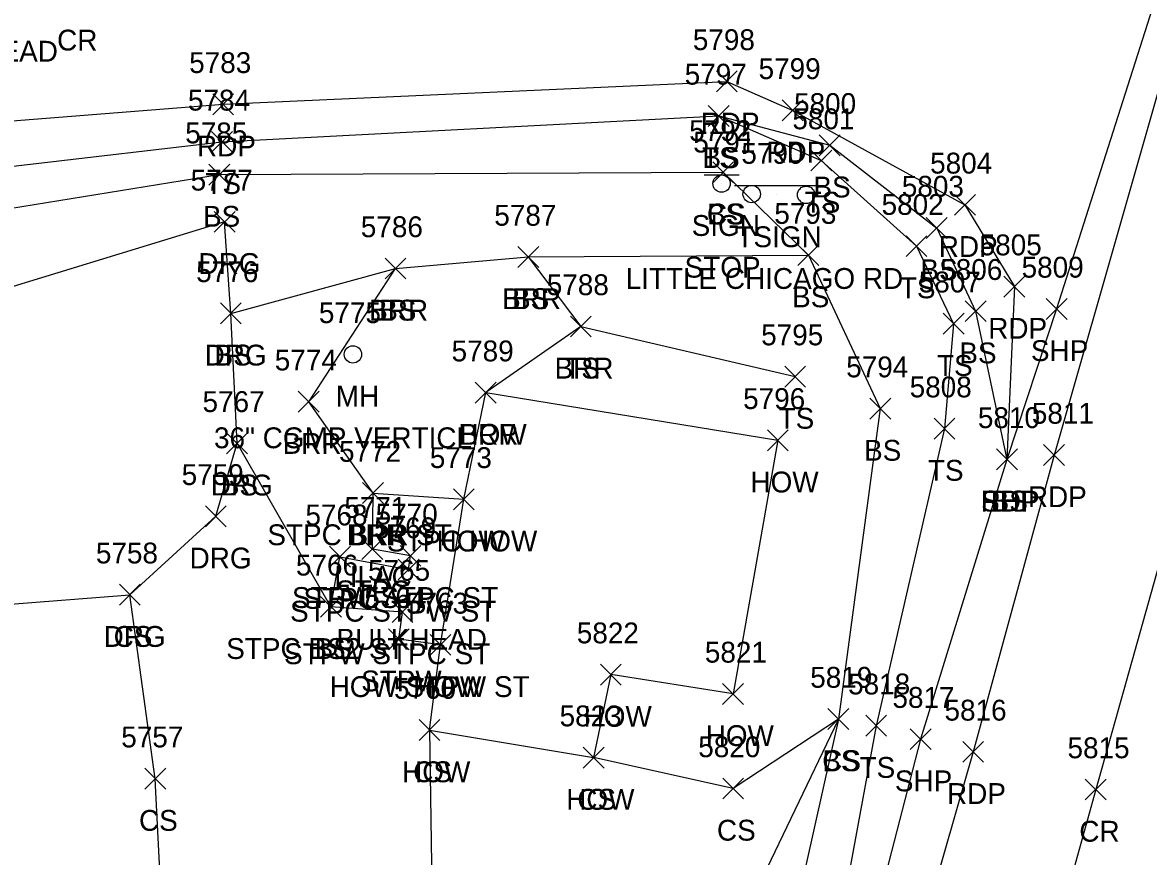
# Model space of a CAD drawing. Extents: x 1443912 to 1445411, y 621446 to 623693.
# Drawn here: x 1444608.9 to 1444716.8, y 622472.5 to 622552.5 of the extents above; entities that cross this region are included whole.
import ezdxf

# ---------------------------------------------------------------- set-up
doc = ezdxf.new("R2010")
doc.units = 0
for name, color, linetype in [('L_A', 7, 'Continuous'), ('L_C', 7, 'Continuous'), ('L_I', 7, 'Continuous'), ('L_TIC', 7, 'Continuous'), ('LABL', 7, 'Continuous'), ('LBC', 7, 'Continuous'), ('LBF', 7, 'Continuous'), ('LELB', 7, 'Continuous'), ('P_A', 7, 'Continuous'), ('P_I', 7, 'Continuous'), ('P_TIC', 7, 'Continuous'), ('PET', 7, 'Continuous'), ('PRC', 7, 'Continuous'), ('PSP', 7, 'Continuous'), ('R_A', 7, 'Continuous'), ('R_I', 7, 'Continuous'), ('R_TIC', 7, 'Continuous'), ('RDG', 7, 'Continuous'), ('S_A', 7, 'Continuous'), ('S_C', 7, 'Continuous'), ('S_I', 7, 'Continuous'), ('SSGN', 7, 'Continuous'), ('U_A', 7, 'Continuous'), ('U_C', 7, 'Continuous'), ('U_I', 7, 'Continuous'), ('UUMH', 7, 'Continuous')]:
    doc.layers.add(name, color=color, linetype=linetype)

msp = doc.modelspace()

# ---------------------------------------------------------------- linework, layer by layer
at = {"layer": 'L_TIC'}
for points in [[(1444674.64, 622542.57), (1444676.64, 622544.57)], [(1444676.64, 622542.57), (1444674.64, 622544.57)], [(1444674.64, 622542.57), (1444676.64, 622544.57)], [(1444676.64, 622542.57), (1444674.64, 622544.57)], [(1444627.03, 622540.08), (1444629.03, 622542.08)], [(1444629.03, 622540.08), (1444627.03, 622542.08)], [(1444685.28, 622539.75), (1444687.28, 622541.75)], [(1444687.28, 622539.75), (1444685.28, 622541.75)], [(1444684.47, 622538.29), (1444686.47, 622540.29)], [(1444686.47, 622538.29), (1444684.47, 622540.29)], [(1444626.77, 622536.94), (1444628.77, 622538.94)], [(1444628.77, 622536.94), (1444626.77, 622538.94)], [(1444675.07, 622537.16), (1444677.07, 622539.16)], [(1444677.07, 622537.16), (1444675.07, 622539.16)], [(1444675.07, 622537.16), (1444677.07, 622539.16)], [(1444677.07, 622537.16), (1444675.07, 622539.16)], [(1444695.53, 622531.82), (1444697.53, 622533.82)], [(1444697.53, 622531.82), (1444695.53, 622533.82)], [(1444693.59, 622530.08), (1444695.59, 622532.08)], [(1444695.59, 622530.08), (1444693.59, 622532.08)], [(1444656.39, 622529.04), (1444658.39, 622531.04)], [(1444658.39, 622529.04), (1444656.39, 622531.04)], [(1444656.39, 622529.04), (1444658.39, 622531.04)], [(1444658.39, 622529.04), (1444656.39, 622531.04)], [(1444683.23, 622529.22), (1444685.23, 622531.22)], [(1444685.23, 622529.22), (1444683.23, 622531.22)], [(1444683.23, 622529.22), (1444685.23, 622531.22)], [(1444685.23, 622529.22), (1444683.23, 622531.22)], [(1444643.66, 622527.94), (1444645.66, 622529.94)], [(1444645.66, 622527.94), (1444643.66, 622529.94)], [(1444643.66, 622527.94), (1444645.66, 622529.94)], [(1444645.66, 622527.94), (1444643.66, 622529.94)], [(1444627.88, 622523.63), (1444629.88, 622525.63)], [(1444629.88, 622523.63), (1444627.88, 622525.63)], [(1444699.26, 622523.84), (1444701.26, 622525.84)], [(1444701.26, 622523.84), (1444699.26, 622525.84)], [(1444661.42, 622522.38), (1444663.42, 622524.38)], [(1444663.42, 622522.38), (1444661.42, 622524.38)], [(1444661.42, 622522.38), (1444663.42, 622524.38)], [(1444663.42, 622522.38), (1444661.42, 622524.38)], [(1444697.15, 622522.64), (1444699.15, 622524.64)], [(1444699.15, 622522.64), (1444697.15, 622524.64)], [(1444681.97, 622517.57), (1444683.97, 622519.57)], [(1444683.97, 622517.57), (1444681.97, 622519.57)], [(1444652.31, 622516.03), (1444654.31, 622518.03)], [(1444654.31, 622516.03), (1444652.31, 622518.03)], [(1444652.31, 622516.03), (1444654.31, 622518.03)], [(1444654.31, 622516.03), (1444652.31, 622518.03)], [(1444635.35, 622515.16), (1444637.35, 622517.16)], [(1444637.35, 622515.16), (1444635.35, 622517.16)], [(1444690.12, 622514.5), (1444692.12, 622516.5)], [(1444692.12, 622514.5), (1444690.12, 622516.5)], [(1444696.28, 622512.58), (1444698.28, 622514.58)], [(1444698.28, 622512.58), (1444696.28, 622514.58)], [(1444628.48, 622511.17), (1444630.48, 622513.17)], [(1444630.48, 622511.17), (1444628.48, 622513.17)], [(1444680.3, 622511.46), (1444682.3, 622513.46)], [(1444682.3, 622511.46), (1444680.3, 622513.46)], [(1444702.26, 622509.63), (1444704.26, 622511.63)], [(1444704.26, 622509.63), (1444702.26, 622511.63)], [(1444641.51, 622506.4), (1444643.51, 622508.4)], [(1444643.51, 622506.4), (1444641.51, 622508.4)], [(1444641.51, 622506.4), (1444643.51, 622508.4)], [(1444643.51, 622506.4), (1444641.51, 622508.4)], [(1444650.21, 622505.8), (1444652.21, 622507.8)], [(1444652.21, 622505.8), (1444650.21, 622507.8)], [(1444650.21, 622505.8), (1444652.21, 622507.8)], [(1444652.21, 622505.8), (1444650.21, 622507.8)], [(1444638.34, 622500.3), (1444640.34, 622502.3)], [(1444640.34, 622500.3), (1444638.34, 622502.3)], [(1444641.45, 622501.02), (1444643.45, 622503.02)], [(1444643.45, 622501.02), (1444641.45, 622503.02)], [(1444645.1, 622500.38), (1444647.1, 622502.38)], [(1444647.1, 622500.38), (1444645.1, 622502.38)], [(1444645.1, 622500.38), (1444647.1, 622502.38)], [(1444647.1, 622500.38), (1444645.1, 622502.38)], [(1444644.92, 622499.07), (1444646.92, 622501.07)], [(1444646.92, 622499.07), (1444644.92, 622501.07)], [(1444644.92, 622499.07), (1444646.92, 622501.07)], [(1444646.92, 622499.07), (1444644.92, 622501.07)], [(1444618.2, 622496.65), (1444620.2, 622498.65)], [(1444620.2, 622496.65), (1444618.2, 622498.65)], [(1444637.48, 622495.49), (1444639.48, 622497.49)], [(1444639.48, 622495.49), (1444637.48, 622497.49)], [(1444637.48, 622495.49), (1444639.48, 622497.49)], [(1444639.48, 622495.49), (1444637.48, 622497.49)], [(1444644.34, 622494.99), (1444646.34, 622496.99)], [(1444646.34, 622494.99), (1444644.34, 622496.99)], [(1444644.34, 622494.99), (1444646.34, 622496.99)], [(1444646.34, 622494.99), (1444644.34, 622496.99)], [(1444643.98, 622492.38), (1444645.98, 622494.38)], [(1444645.98, 622492.38), (1444643.98, 622494.38)], [(1444647.97, 622491.84), (1444649.97, 622493.84)], [(1444649.97, 622491.84), (1444647.97, 622493.84)], [(1444647.97, 622491.84), (1444649.97, 622493.84)], [(1444649.97, 622491.84), (1444647.97, 622493.84)], [(1444664.3, 622488.99), (1444666.3, 622490.99)], [(1444666.3, 622488.99), (1444664.3, 622490.99)], [(1444676.01, 622487.14), (1444678.01, 622489.14)], [(1444678.01, 622487.14), (1444676.01, 622489.14)], [(1444686.11, 622484.73), (1444688.11, 622486.73)], [(1444688.11, 622484.73), (1444686.11, 622486.73)], [(1444686.11, 622484.73), (1444688.11, 622486.73)], [(1444688.11, 622484.73), (1444686.11, 622486.73)], [(1444686.11, 622484.73), (1444688.11, 622486.73)], [(1444688.11, 622484.73), (1444686.11, 622486.73)], [(1444689.73, 622484.09), (1444691.73, 622486.09)], [(1444691.73, 622484.09), (1444689.73, 622486.09)], [(1444646.92, 622483.67), (1444648.92, 622485.67)], [(1444648.92, 622483.67), (1444646.92, 622485.67)], [(1444646.92, 622483.67), (1444648.92, 622485.67)], [(1444648.92, 622483.67), (1444646.92, 622485.67)], [(1444646.92, 622483.67), (1444648.92, 622485.67)], [(1444648.92, 622483.67), (1444646.92, 622485.67)], [(1444662.65, 622481.03), (1444664.65, 622483.03)], [(1444664.65, 622481.03), (1444662.65, 622483.03)], [(1444662.65, 622481.03), (1444664.65, 622483.03)], [(1444664.65, 622481.03), (1444662.65, 622483.03)], [(1444662.65, 622481.03), (1444664.65, 622483.03)], [(1444664.65, 622481.03), (1444662.65, 622483.03)], [(1444620.64, 622479.01), (1444622.64, 622481.01)], [(1444622.64, 622479.01), (1444620.64, 622481.01)], [(1444676.02, 622478.07), (1444678.02, 622480.07)], [(1444678.02, 622478.07), (1444676.02, 622480.07)]]:
    msp.add_lwpolyline(points, dxfattribs=at)
at = {"layer": 'LABL'}
msp.add_lwpolyline([(1444642.51, 622507.4), (1444636.35, 622516.16), (1444644.66, 622528.94), (1444657.39, 622530.04), (1444662.42, 622523.38), (1444653.31, 622517.03)], dxfattribs=at)
at = {"layer": 'LBC'}
for points in [[(1444647.92, 622484.67), (1444648.97, 622492.84), (1444651.21, 622506.8), (1444653.31, 622517.03), (1444681.3, 622512.46), (1444677.01, 622488.14), (1444665.3, 622489.99), (1444663.65, 622482.03)], [(1444647.92, 622484.67), (1444663.65, 622482.03)]]:
    msp.add_lwpolyline(points, dxfattribs=at)
at = {"layer": 'LBF'}
for points in [[(1444646.1, 622501.38), (1444642.45, 622502.02), (1444642.51, 622507.4), (1444651.21, 622506.8)], [(1444645.34, 622495.99), (1444638.48, 622496.49), (1444639.34, 622501.3), (1444645.92, 622500.07)], [(1444645.92, 622500.07), (1444646.1, 622501.38)], [(1444648.97, 622492.84), (1444644.98, 622493.38), (1444645.34, 622495.99)]]:
    msp.add_lwpolyline(points, dxfattribs=at)
at = {"layer": 'LELB'}
for points in [[(1444421.11, 622504.89), (1444418.48, 622504.7), (1444415.25, 622506.32), (1444414.67, 622509.11), (1444420.34, 622517.15), (1444423.31, 622521.52), (1444460.25, 622525.5), (1444495.17, 622528.66), (1444538.07, 622531.66), (1444573.03, 622534.31), (1444590.73, 622536.75), (1444628.03, 622541.08), (1444675.64, 622543.57), (1444685.47, 622539.29), (1444694.59, 622531.08), (1444698.15, 622523.64), (1444697.28, 622513.58), (1444690.73, 622485.09), (1444685.42, 622456.27), (1444672.73, 622423.51)], [(1444675.64, 622543.57), (1444686.28, 622540.75), (1444696.53, 622532.82), (1444700.26, 622524.84), (1444703.26, 622510.63)], [(1444409.34, 622487.42), (1444415.25, 622506.32), (1444423.16, 622515.73), (1444423.35, 622517.79), (1444427.35, 622519.19), (1444459.99, 622522.27), (1444495.92, 622525.45), (1444537.82, 622527.87), (1444575.08, 622531.37), (1444592.28, 622532.21), (1444627.77, 622537.94), (1444676.07, 622538.16), (1444684.23, 622530.22)], [(1444657.39, 622530.04), (1444684.23, 622530.22), (1444691.12, 622515.5), (1444687.11, 622485.73), (1444673.41, 622457.14), (1444667.38, 622434.95)], [(1444628.88, 622524.63), (1444644.66, 622528.94)], [(1444662.42, 622523.38), (1444682.97, 622518.57)], [(1444638.48, 622496.49), (1444629.48, 622512.17)], [(1444626.49, 622431.4), (1444625.7, 622446.49), (1444622.58, 622461.12), (1444621.64, 622480.01), (1444619.2, 622497.65)], [(1444687.11, 622485.73), (1444681.71, 622461.51), (1444668.63, 622426.69), (1444649.03, 622429.73), (1444633.61, 622428.6)], [(1444687.11, 622485.73), (1444677.02, 622479.07), (1444663.65, 622482.03)], [(1444647.92, 622484.67), (1444648.26, 622461.14), (1444648.76, 622435.33)]]:
    msp.add_lwpolyline(points, dxfattribs=at)
at = {"layer": 'P_TIC'}
for points in [[(1444675.42, 622545.88), (1444677.42, 622547.88)], [(1444677.42, 622545.88), (1444675.42, 622547.88)], [(1444627.15, 622543.68), (1444629.15, 622545.68)], [(1444629.15, 622543.68), (1444627.15, 622545.68)], [(1444681.73, 622543.1), (1444683.73, 622545.1)], [(1444683.73, 622543.1), (1444681.73, 622545.1)], [(1444698.24, 622534.04), (1444700.24, 622536.04)], [(1444700.24, 622534.04), (1444698.24, 622536.04)], [(1444702.98, 622526.2), (1444704.98, 622528.2)], [(1444704.98, 622526.2), (1444702.98, 622528.2)], [(1444707.02, 622524.06), (1444709.02, 622526.06)], [(1444709.02, 622524.06), (1444707.02, 622526.06)], [(1444707.02, 622524.06), (1444709.02, 622526.06)], [(1444709.02, 622524.06), (1444707.02, 622526.06)], [(1444706.78, 622510.05), (1444708.78, 622512.05)], [(1444708.78, 622510.05), (1444706.78, 622512.05)], [(1444706.78, 622510.05), (1444708.78, 622512.05)], [(1444708.78, 622510.05), (1444706.78, 622512.05)], [(1444702.26, 622509.63), (1444704.26, 622511.63)], [(1444704.26, 622509.63), (1444702.26, 622511.63)], [(1444702.26, 622509.63), (1444704.26, 622511.63)], [(1444704.26, 622509.63), (1444702.26, 622511.63)], [(1444693.99, 622482.8), (1444695.99, 622484.8)], [(1444695.99, 622482.8), (1444693.99, 622484.8)], [(1444699.03, 622481.58), (1444701.03, 622483.58)], [(1444701.03, 622481.58), (1444699.03, 622483.58)], [(1444710.77, 622477.97), (1444712.77, 622479.97)], [(1444712.77, 622477.97), (1444710.77, 622479.97)]]:
    msp.add_lwpolyline(points, dxfattribs=at)
at = {"layer": 'PET'}
for points in [[(1444737.32, 622616.48), (1444732.68, 622599.46), (1444722.11, 622561.15), (1444707.78, 622511.05)], [(1443922.89, 622481.78), (1443964.16, 622485.92), (1444013.47, 622490.18), (1444063.08, 622494.61), (1444083.54, 622496.56), (1444116.52, 622499.25), (1444168.09, 622503.58), (1444210.27, 622507.18), (1444250.99, 622510.56), (1444300.66, 622515.16), (1444342.9, 622518.95), (1444378.71, 622522.5), (1444430.26, 622526.78), (1444460.19, 622529.88), (1444494.98, 622532.7), (1444537.07, 622536.56), (1444563.09, 622539.1), (1444595.4, 622542.11), (1444628.15, 622544.68), (1444676.42, 622546.88), (1444682.73, 622544.1), (1444699.24, 622535.04), (1444703.98, 622527.2), (1444703.26, 622510.63)], [(1444707.78, 622511.05), (1444700.03, 622482.58), (1444691.73, 622453.67), (1444679.73, 622411.23), (1444667.69, 622368.84), (1444653.08, 622317.67), (1444637.74, 622256.92), (1444626.42, 622209.58), (1444619.02, 622182.67), (1444605.37, 622130.08), (1444589.4, 622078.61), (1444578.44, 622026.86), (1444565.52, 621990.05), (1444556.87, 621958.17), (1444542.16, 621907.74), (1444529.8, 621863.07), (1444511.99, 621799.88), (1444498.16, 621751.76), (1444483.13, 621697.3), (1444470.84, 621653.16), (1444463.41, 621627.34), (1444449.07, 621575.52), (1444430.26, 621508.83), (1444421.17, 621471.46)]]:
    msp.add_lwpolyline(points, dxfattribs=at)
at = {"layer": 'PRC'}
msp.add_lwpolyline([(1444846.73, 622950.74), (1444829.37, 622896.11), (1444814.12, 622840.53), (1444801.7, 622795.63), (1444790.08, 622753.54), (1444778.65, 622716.11), (1444769.12, 622683.18), (1444760.94, 622654.81), (1444750.77, 622619.03), (1444741.67, 622586.01), (1444729.73, 622541.23), (1444723.42, 622520.39), (1444711.77, 622478.97), (1444703.65, 622449.63), (1444691.66, 622407.43), (1444679.51, 622365.85), (1444664.93, 622313.64), (1444649.43, 622253.98), (1444637.04, 622206.21), (1444631.31, 622178.74), (1444618.32, 622127.38), (1444604.97, 622075.74)], dxfattribs=at)
at = {"layer": 'PSP'}
for points in [[(1444735.15, 622617.37), (1444730.87, 622600.03), (1444727.75, 622590.13), (1444719.77, 622561.99), (1444708.02, 622525.06)], [(1444708.02, 622525.06), (1444703.26, 622510.63), (1444694.99, 622483.8), (1444687.65, 622455.43), (1444679.42, 622427.15), (1444669.36, 622395.79), (1444665.29, 622376.89), (1444648.73, 622318.09), (1444646.34, 622310.05), (1444631.38, 622258.8), (1444618.63, 622212.47), (1444610.54, 622185.48), (1444596.17, 622132.46), (1444585.6, 622096.58)]]:
    msp.add_lwpolyline(points, dxfattribs=at)
at = {"layer": 'R_TIC'}
for points in [[(1444627.29, 622532.41), (1444629.29, 622534.41)], [(1444629.29, 622532.41), (1444627.29, 622534.41)], [(1444627.88, 622523.63), (1444629.88, 622525.63)], [(1444629.88, 622523.63), (1444627.88, 622525.63)], [(1444628.48, 622511.17), (1444630.48, 622513.17)], [(1444630.48, 622511.17), (1444628.48, 622513.17)], [(1444626.44, 622504.17), (1444628.44, 622506.17)], [(1444628.44, 622504.17), (1444626.44, 622506.17)], [(1444618.2, 622496.65), (1444620.2, 622498.65)], [(1444620.2, 622496.65), (1444618.2, 622498.65)]]:
    msp.add_lwpolyline(points, dxfattribs=at)
at = {"layer": 'RDG'}
msp.add_lwpolyline([(1444582.15, 622486.18), (1444599.95, 622488.7), (1444599.13, 622496.08), (1444619.2, 622497.65), (1444627.44, 622505.17), (1444629.48, 622512.17), (1444628.88, 622524.63), (1444628.29, 622533.41), (1444602.15, 622525.41), (1444592.28, 622532.21), (1444590.73, 622536.75), (1444590.12, 622540.23)], dxfattribs=at)
at = {"layer": 'SSGN'}
for p, q in [((1444674.26, 622537.91), (1444677.59, 622537.91)), ((1444675.91, 622537.08), (1444675.91, 622537.08)), ((1444677.14, 622536.9), (1444685.74, 622536.9)), ((1444681.16, 622536), (1444681.16, 622536))]:
    msp.add_line(p, q, dxfattribs=at)
for centre in [(1444675.91, 622537.08), (1444678.8, 622536.07), (1444684.02, 622536)]:
    msp.add_circle(centre, 0.833, dxfattribs=at)
at = {"layer": 'UUMH'}
for p, q in [((1444640.58, 622520.7), (1444640.58, 622520.7)), ((1444641.41, 622520.7), (1444641.41, 622520.7))]:
    msp.add_line(p, q, dxfattribs=at)
msp.add_circle((1444640.58, 622520.7), 0.833, dxfattribs=at)

# ---------------------------------------------------------------- texts
at = {"layer": 'L_A'}
for s, p in [('TS', (1444674.05, 622538.57)), ('BS', (1444674.08, 622538.57)), ('TS', (1444626.44, 622536.08)), ('BS', (1444684.72, 622535.75)), ('TS', (1444683.88, 622534.29)), ('BS', (1444626.21, 622532.94)), ('CS', (1444674.51, 622533.16)), ('BS', (1444674.51, 622533.16)), ('BS', (1444694.97, 622527.82)), ('BS', (1444655.83, 622525.04)), ('BS', (1444682.67, 622525.22)), ('BS', (1444682.67, 622525.22)), ('TS', (1444693, 622526.08)), ('BS', (1444643.1, 622523.94)), ('BRR', (1444654.88, 622525.04)), ('BRR', (1444642.14, 622523.94)), ('BS', (1444627.32, 622519.63)), ('BS', (1444698.7, 622519.84)), ('TS', (1444696.56, 622518.64)), ('BRR', (1444659.91, 622518.38)), ('TS', (1444660.83, 622518.38)), ('TS', (1444681.38, 622513.57)), ('BRR', (1444633.84, 622511.16)), ('HOW', (1444650.7, 622512.03)), ('BRR', (1444650.8, 622512.03)), ('BS', (1444689.57, 622510.5)), ('TS', (1444695.69, 622508.58)), ('BS', (1444627.92, 622507.17)), ('HOW', (1444678.68, 622507.46)), ('BS', (1444701.7, 622505.63)), ('STPC BRR ST', (1444632.38, 622502.4)), ('BRR', (1444640, 622502.4)), ('STPC HOW', (1444643.84, 622501.8)), ('HOW', (1444648.6, 622501.8)), ('STPC', (1444638.96, 622497.02)), ('STPW STPC ST', (1444634.74, 622496.38)), ('STPW STPC ST', (1444634.74, 622496.38)), ('STPC', (1444635.85, 622496.3)), ('STPC STPW ST', (1444634.56, 622495.07)), ('STPC STPW ST', (1444634.56, 622495.07)), ('CS', (1444617.65, 622492.65)), ('STPC BS2 ST', (1444628.44, 622491.49)), ('STPW STPC ST', (1444633.98, 622490.99)), ('STPW STPC ST', (1444633.98, 622490.99)), ('BS', (1444636.92, 622491.49)), ('STPW', (1444641.37, 622488.38)), ('HOW STPW ST', (1444638.35, 622487.84)), ('HOW', (1444646.36, 622487.84)), ('HOW', (1444662.69, 622484.99)), ('HOW', (1444674.39, 622483.14)), ('CS', (1444685.56, 622480.73)), ('CS', (1444685.56, 622480.73)), ('BS', (1444685.56, 622480.73)), ('TS', (1444689.14, 622480.09)), ('HOW', (1444645.3, 622479.67)), ('HOW', (1444645.3, 622479.67)), ('CS', (1444646.36, 622479.67)), ('HOW', (1444661.03, 622477.03)), ('HOW', (1444661.03, 622477.03)), ('CS', (1444662.09, 622477.03)), ('CS', (1444620.08, 622475.01)), ('CS', (1444675.47, 622474.07))]:
    msp.add_text(s, height=2, dxfattribs=at).set_placement(p)
at = {"layer": 'L_C'}
for s, p in [('LILAC', (1444638.79, 622498.4)), ('BULKHEAD', (1444639.01, 622492.38)), ('BULKHEAD', (1444639.01, 622492.38))]:
    msp.add_text(s, height=2, dxfattribs=at).set_placement(p)
at = {"layer": 'L_I'}
for s, p in [('5797', (1444672.38, 622546.57)), ('5797', (1444672.38, 622546.57)), ('5784', (1444624.77, 622544.08)), ('5800', (1444682.86, 622543.75)), ('5801', (1444682.7, 622542.29)), ('5785', (1444624.51, 622540.94)), ('5792', (1444672.81, 622541.16)), ('5792', (1444672.81, 622541.16)), ('5803', (1444693.19, 622535.82)), ('5802', (1444691.25, 622534.08)), ('5787', (1444654.13, 622533.04)), ('5787', (1444654.13, 622533.04)), ('5793', (1444680.97, 622533.22)), ('5793', (1444680.97, 622533.22)), ('5786', (1444641.34, 622531.94)), ('5786', (1444641.34, 622531.94)), ('5776', (1444625.56, 622527.63)), ('5806', (1444696.87, 622527.84)), ('5788', (1444659.16, 622526.38)), ('5788', (1444659.16, 622526.38)), ('5807', (1444694.81, 622526.64)), ('5795', (1444679.71, 622521.57)), ('5789', (1444650.04, 622520.03)), ('5789', (1444650.04, 622520.03)), ('5774', (1444633.09, 622519.16)), ('5794', (1444687.86, 622518.5)), ('5808', (1444693.94, 622516.58)), ('5796', (1444677.98, 622515.46)), ('5767', (1444626.17, 622515.17)), ('5810', (1444700.48, 622513.63)), ('5772', (1444639.25, 622510.4)), ('5772', (1444639.25, 622510.4)), ('5773', (1444647.95, 622509.8)), ('5773', (1444647.95, 622509.8)), ('5771', (1444639.76, 622505.02)), ('5768', (1444636.03, 622504.3)), ('5770', (1444642.76, 622504.38)), ('5770', (1444642.76, 622504.38)), ('5769', (1444642.61, 622503.07)), ('5769', (1444642.61, 622503.07)), ('5758', (1444615.95, 622500.65)), ('5766', (1444635.12, 622499.49)), ('5766', (1444635.12, 622499.49)), ('5765', (1444642.03, 622498.99)), ('5765', (1444642.03, 622498.99)), ('5764', (1444641.67, 622496.38)), ('5763', (1444645.67, 622495.84)), ('5763', (1444645.67, 622495.84)), ('5822', (1444662.04, 622492.99)), ('5821', (1444674.31, 622491.14)), ('5819', (1444684.41, 622488.73)), ('5819', (1444684.41, 622488.73)), ('5819', (1444684.41, 622488.73)), ('5760', (1444644.52, 622487.67)), ('5760', (1444644.52, 622487.67)), ('5760', (1444644.52, 622487.67)), ('5818', (1444688.04, 622488.09)), ('5823', (1444660.39, 622485.03)), ('5823', (1444660.39, 622485.03)), ('5823', (1444660.39, 622485.03)), ('5757', (1444618.38, 622483.01)), ('5820', (1444673.68, 622482.07))]:
    msp.add_text(s, height=2, dxfattribs=at).set_placement(p)
at = {"layer": 'P_A'}
for s, p in [('CR', (1444612.23, 622549.84)), ('RDP', (1444673.91, 622541.88)), ('RDP', (1444625.64, 622539.68)), ('RDP', (1444680.21, 622539.1)), ('RDP', (1444696.73, 622530.04)), ('RDP', (1444701.47, 622522.2)), ('SHP', (1444705.56, 622520.06)), ('SHP', (1444705.56, 622520.06)), ('SHP', (1444700.79, 622505.63)), ('RDP', (1444700.75, 622505.63)), ('RDP', (1444705.27, 622506.05)), ('RDP', (1444705.27, 622506.05)), ('SHP', (1444692.52, 622478.8)), ('RDP', (1444697.52, 622477.58)), ('CR', (1444710.2, 622473.97))]:
    msp.add_text(s, height=2, dxfattribs=at).set_placement(p)
at = {"layer": 'P_I'}
for s, p in [('5798', (1444673.16, 622549.88)), ('5783', (1444624.89, 622547.68)), ('5799', (1444679.46, 622547.1)), ('5804', (1444695.9, 622538.04)), ('5805', (1444700.65, 622530.2)), ('5809', (1444704.67, 622528.06)), ('5809', (1444704.67, 622528.06)), ('5810', (1444700.48, 622513.63)), ('5810', (1444700.48, 622513.63)), ('5811', (1444705.65, 622514.05)), ('5811', (1444705.65, 622514.05)), ('5817', (1444692.29, 622486.8)), ('5816', (1444697.28, 622485.58)), ('5815', (1444709.07, 622481.97))]:
    msp.add_text(s, height=2, dxfattribs=at).set_placement(p)
at = {"layer": 'R_A'}
for p in [(1444625.78, 622528.41), (1444626.37, 622519.63), (1444626.96, 622507.17), (1444624.93, 622500.17), (1444616.69, 622492.65)]:
    msp.add_text('DRG', height=2, dxfattribs=at).set_placement(p)
at = {"layer": 'R_I'}
for s, p in [('5777', (1444625.03, 622536.41)), ('5776', (1444625.56, 622527.63)), ('5767', (1444626.17, 622515.17)), ('5759', (1444624.17, 622508.17)), ('5758', (1444615.95, 622500.65))]:
    msp.add_text(s, height=2, dxfattribs=at).set_placement(p)
at = {"layer": 'S_A'}
for s, p in [('SIGN', (1444673.05, 622532.06)), ('TSIGN', (1444677.34, 622530.98))]:
    msp.add_text(s, height=2, dxfattribs=at).set_placement(p)
at = {"layer": 'S_C'}
for s, p in [('STOP', (1444672.37, 622528.06)), ('LITTLE CHICAGO RD', (1444666.72, 622526.98))]:
    msp.add_text(s, height=2, dxfattribs=at).set_placement(p)
at = {"layer": 'S_I'}
for s, p in [('5791', (1444673.2, 622540.06)), ('5790', (1444677.81, 622538.98))]:
    msp.add_text(s, height=2, dxfattribs=at).set_placement(p)
at = {"layer": 'U_A'}
for s, p in [('OVERHEAD', (1444597.3, 622548.77)), ('MH', (1444638.94, 622515.7))]:
    msp.add_text(s, height=2, dxfattribs=at).set_placement(p)
at = {"layer": 'U_C'}
msp.add_text('36" CGMP VERTICL', height=2, dxfattribs=at).set_placement((1444627.27, 622511.7))
at = {"layer": 'U_I'}
msp.add_text('5775', height=2, dxfattribs=at).set_placement((1444637.32, 622523.7))

doc.saveas('drawing.dxf')
